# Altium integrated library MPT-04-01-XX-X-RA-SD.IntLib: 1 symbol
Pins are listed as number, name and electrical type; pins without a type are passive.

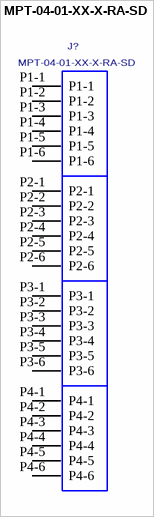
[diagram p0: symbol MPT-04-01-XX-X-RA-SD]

## MPT-04-01-XX-X-RA-SD
designator J?
RIGHT ANGLE MINI-POWER TERMINAL.; MANUFACTURER: SAMTEC
footprint MPT-04-01-XX-X-RA-SD
pins: P1-1, P1-2, P1-3, P1-4, P1-5, P1-6, P2-1, P2-2, P2-3, P2-4, P2-5, P2-6, P3-1, P3-2, P3-3, P3-4, P3-5, P3-6, P4-1, P4-2, P4-3, P4-4, P4-5, P4-6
